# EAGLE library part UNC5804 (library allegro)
BiMOS II UNIPOLAR STEPPER-MOTOR TRANSLATOR/DRIVER Source: 5804.pdf
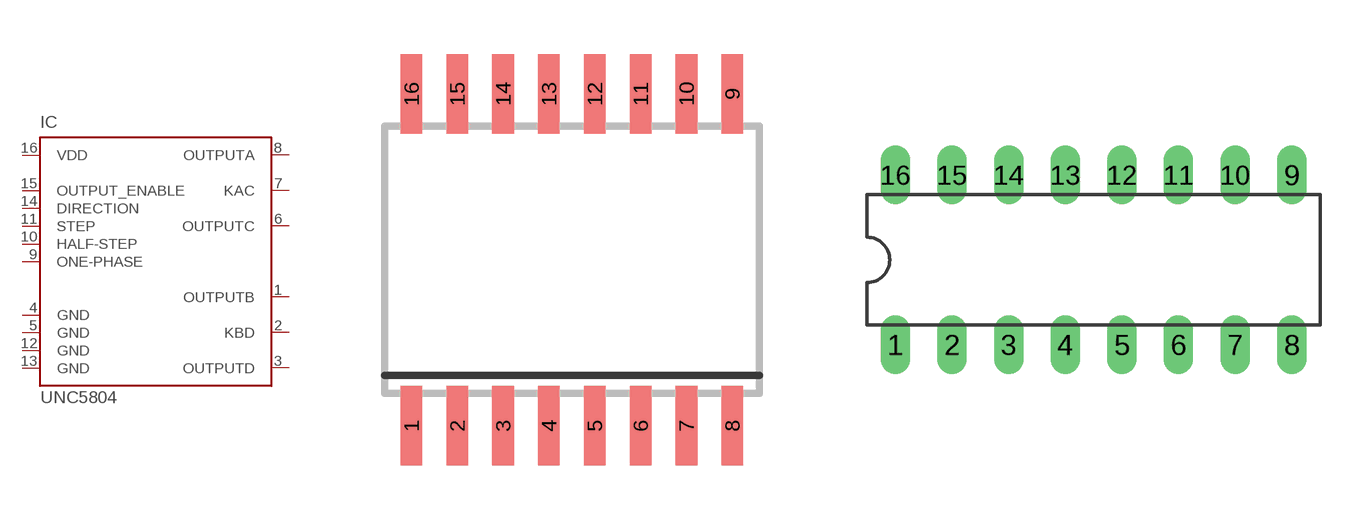
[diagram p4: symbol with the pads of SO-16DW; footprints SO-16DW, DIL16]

Designator prefix IC

## UNC5804LB (OC_FARNELL: unknown; OC_NEWARK: unknown)  [SO-16DW]
1  OUTPUTB  out
2  KBD  pas
3  OUTPUTD  out
4  GND  pwr
5  GND  pwr
6  OUTPUTC  out
7  KAC  pas
8  OUTPUTA  out
9  ONE-PHASE  in
10  HALF-STEP  in
11  STEP  in
12  GND  pwr
13  GND  pwr
14  DIRECTION  in
15  OUTPUT_ENABLE  in
16  VDD  pwr

## UNC5804B (OC_FARNELL: unknown; OC_NEWARK: unknown)  [DIL16]
Pads as for SO-16DW

## Footprint SO-16DW (pad centres in mm)
Small Outline Integrated Circuit wide
smd 0.6 x 2.2: 1 -4.445,-4.6; 2 -3.175,-4.6; 3 -1.905,-4.6; 4 -0.635,-4.6; 5 0.635,-4.6; 6 1.905,-4.6; 7 3.175,-4.6; 8 4.445,-4.6; 9 4.445,4.6; 10 3.175,4.6; 11 1.905,4.6; 12 0.635,4.6; 13 -0.635,4.6; 14 -1.905,4.6; 15 -3.175,4.6; 16 -4.445,4.6

## Footprint DIL16 (pad centres in mm)
Dual In Line Package
drill 0.813 long: 1 -8.89,-3.81; 2 -6.35,-3.81; 3 -3.81,-3.81; 4 -1.27,-3.81; 5 1.27,-3.81; 6 3.81,-3.81; 7 6.35,-3.81; 8 8.89,-3.81; 9 8.89,3.81; 10 6.35,3.81; 11 3.81,3.81; 12 1.27,3.81; 13 -1.27,3.81; 14 -3.81,3.81; 15 -6.35,3.81; 16 -8.89,3.81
